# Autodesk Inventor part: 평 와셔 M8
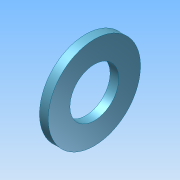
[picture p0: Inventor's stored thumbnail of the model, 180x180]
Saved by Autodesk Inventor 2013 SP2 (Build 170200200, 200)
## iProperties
Created: 2025-10
Part Number: 평 와셔 M8
Material: Generic
Document SubType Name: Modeling
Designer: a
Density: 1 g/cm^3
Author: a
변환 표준: STEP AP214IS
전처리기: Build: 200, Release: 2013 SP2 Update 6 - Date: Thu 07/17/2014
전송 단위: 밀리미터
불확실성: 0.01
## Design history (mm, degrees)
node "평 와셔 M81"
body "Solid1"
node "기준1"
